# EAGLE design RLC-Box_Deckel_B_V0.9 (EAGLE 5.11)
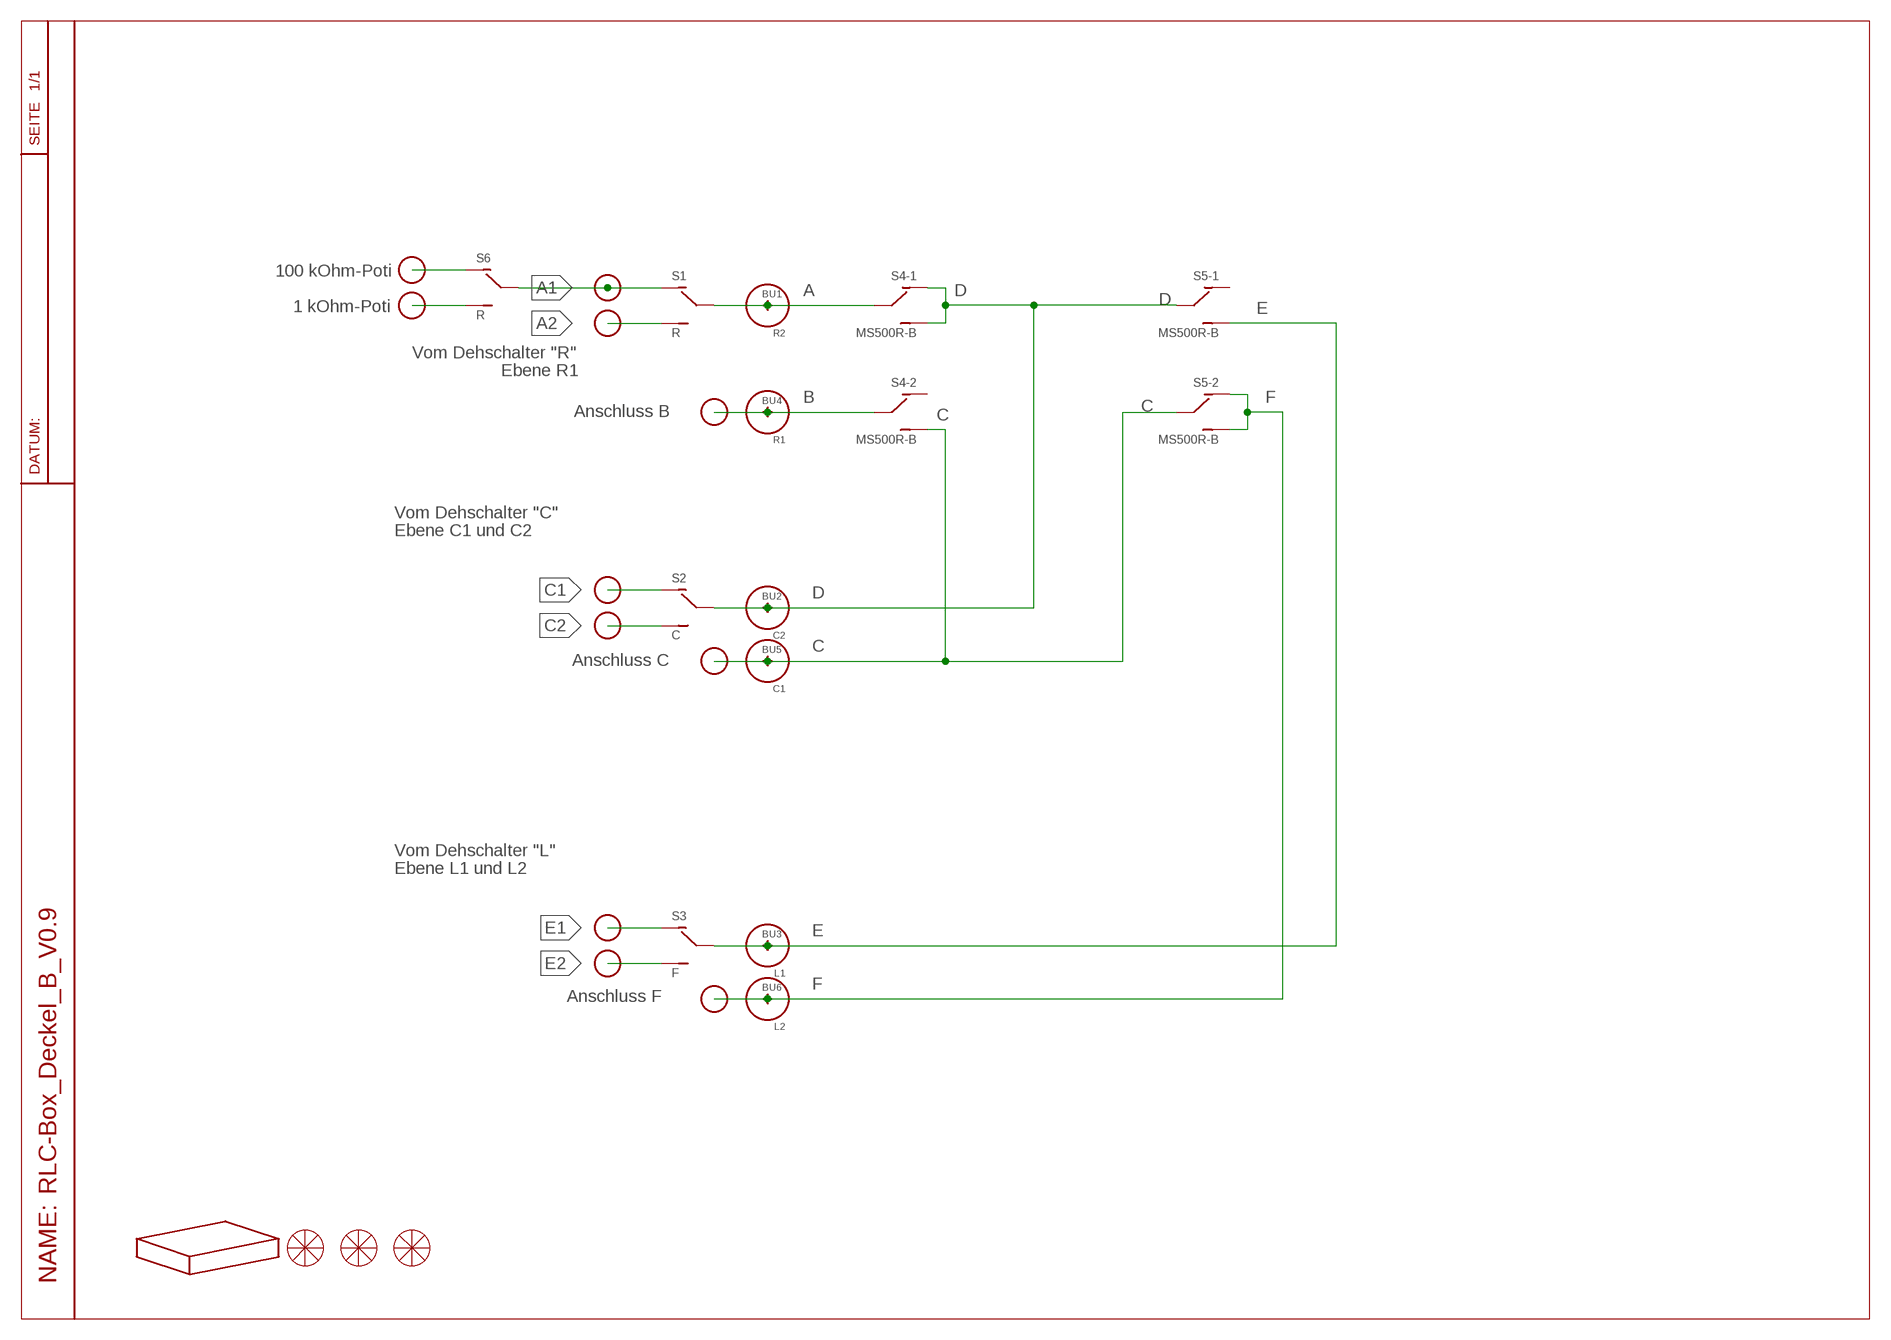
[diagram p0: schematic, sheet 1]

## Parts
BU1  R2  PK10AP  [PK10AP]
BU2  C2  PK10AP  [PK10AP]
BU3  L1  PK10AP  [PK10AP]
BU4  R1  PK10AP  [PK10AP]
BU5  C1  PK10AP  [PK10AP]
BU6  L2  PK10AP  [PK10AP]
P1  PAD-01  PAD-01SMD  [PAD-01-SMD]
P2  PAD-01  PAD-01SMD  [PAD-01-SMD]
P3  PAD-01  PAD-01SMD  [PAD-01-SMD]
P4  PAD-01  PAD-01SMD  [PAD-01-SMD]
P5  PAD-01  PAD-01SMD  [PAD-01-SMD]
P6  PAD-01  PAD-01SMD  [PAD-01-SMD]
P7  PAD-01  PAD-01SMD  [PAD-01-SMD]
P8  PAD-01  PAD-01SMD  [PAD-01-SMD]
P9  PAD-01  PAD-01SMD  [PAD-01-SMD]
P10  PAD-01  PAD-01SMD  [PAD-01-SMD]
P11  PAD-01  PAD-01SMD  [PAD-01-SMD]
S1  R  1XUMT1813  [T8013-1XUM]
S2  C  1XUMT1813  [T8013-1XUM]
S3  F  1XUMT1813  [T8013-1XUM]
S4  MS500R-B  MS500R-BT8011  [T8011-2XUM]
S5  MS500R-B  MS500R-BT8011  [T8011-2XUM]
S6  R  1XUMT1813  [T8013-1XUM]
U$1  DECKEL  [GEHÄUSE]
U$5  SKALA24  SKALA24K  [SKALE24]
U$6  SKALA24  SKALA24K  [SKALE24]
U$9  SKALA24  SKALA24G  [SKALE25-2]

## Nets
A: BU1.1 S1.2 S4.2
A1: P1.P$1 S1.1 S6.2
A2: P2.P$1 S1.3
B: BU4.1 P3.P$1 S4.5
C: BU5.1 P6.P$1 S4.6 S5.5
C1: P4.P$1 S2.1
C2: P5.P$1 S2.3
D: BU2.1 S2.2 S4.1 S4.3 S5.2
E: BU3.1 S3.2 S5.3
E1: P7.P$1 S3.1
E2: P8.P$1 S3.3
F: BU6.1 P9.P$1 S5.4 S5.6
N$1: P10.P$1 S6.1
N$2: P11.P$1 S6.3
Unconnected: S4.4 S5.1

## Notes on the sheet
- 100 kOhm-Poti
- 1 kOhm-Poti
- Vom Dehschalter "R"
- Ebene R1
- Anschluss B
- Vom Dehschalter "C"
- Ebene C1 und C2
- Anschluss C
- Vom Dehschalter "L"
- Ebene L1 und L2
- Anschluss F

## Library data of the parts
BU1-BU6 = MB:PK10AP
P1-P11 = Connect:PAD-01
S1-S3 S6 = Schalter:1XUM
S4 S5 = Schalter:MS500R-B
U$1 = RLC-BOX:DECKEL
U$5 U$6 U$9 = RLC-BOX:SKALA24

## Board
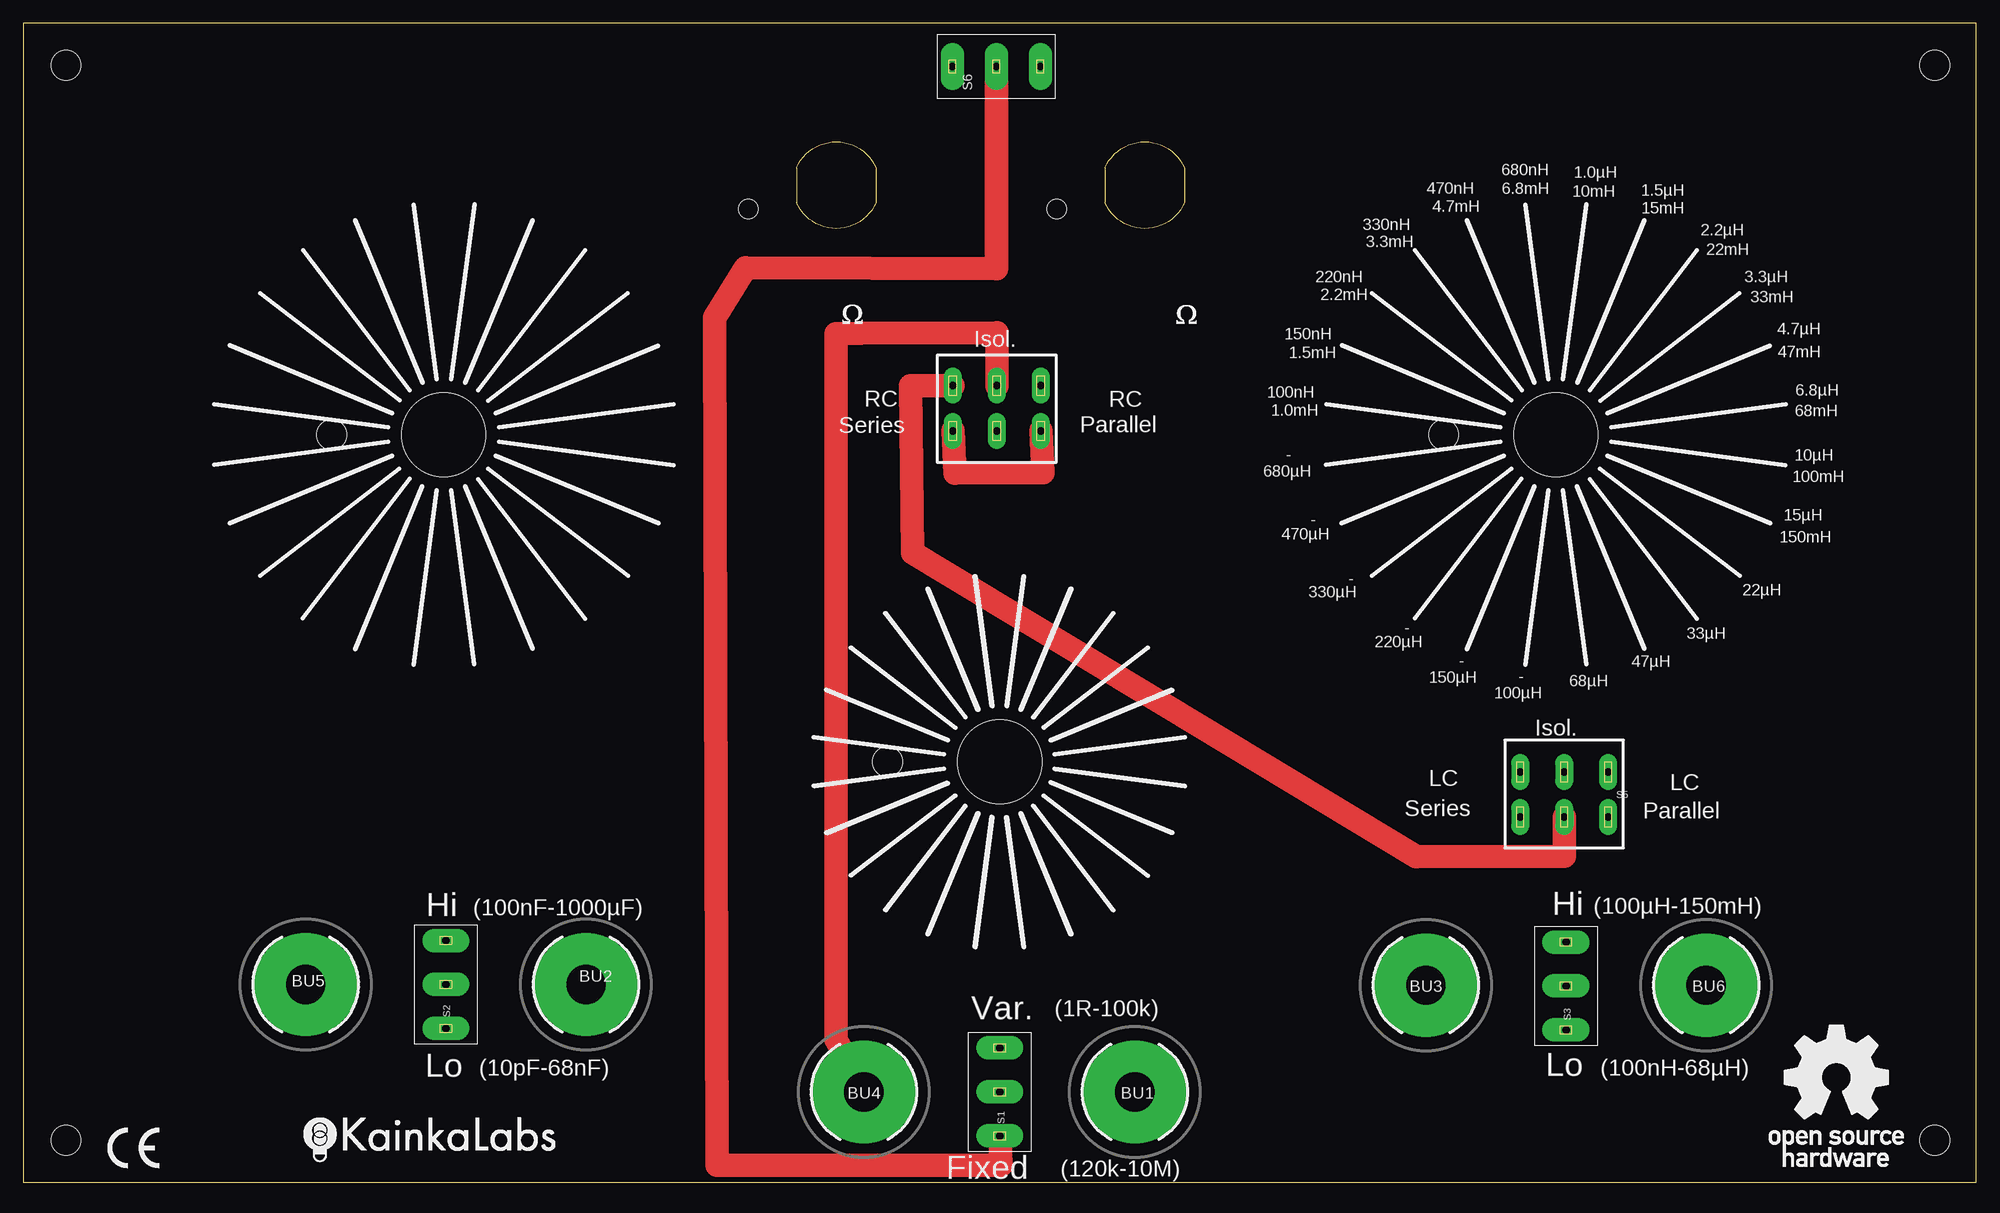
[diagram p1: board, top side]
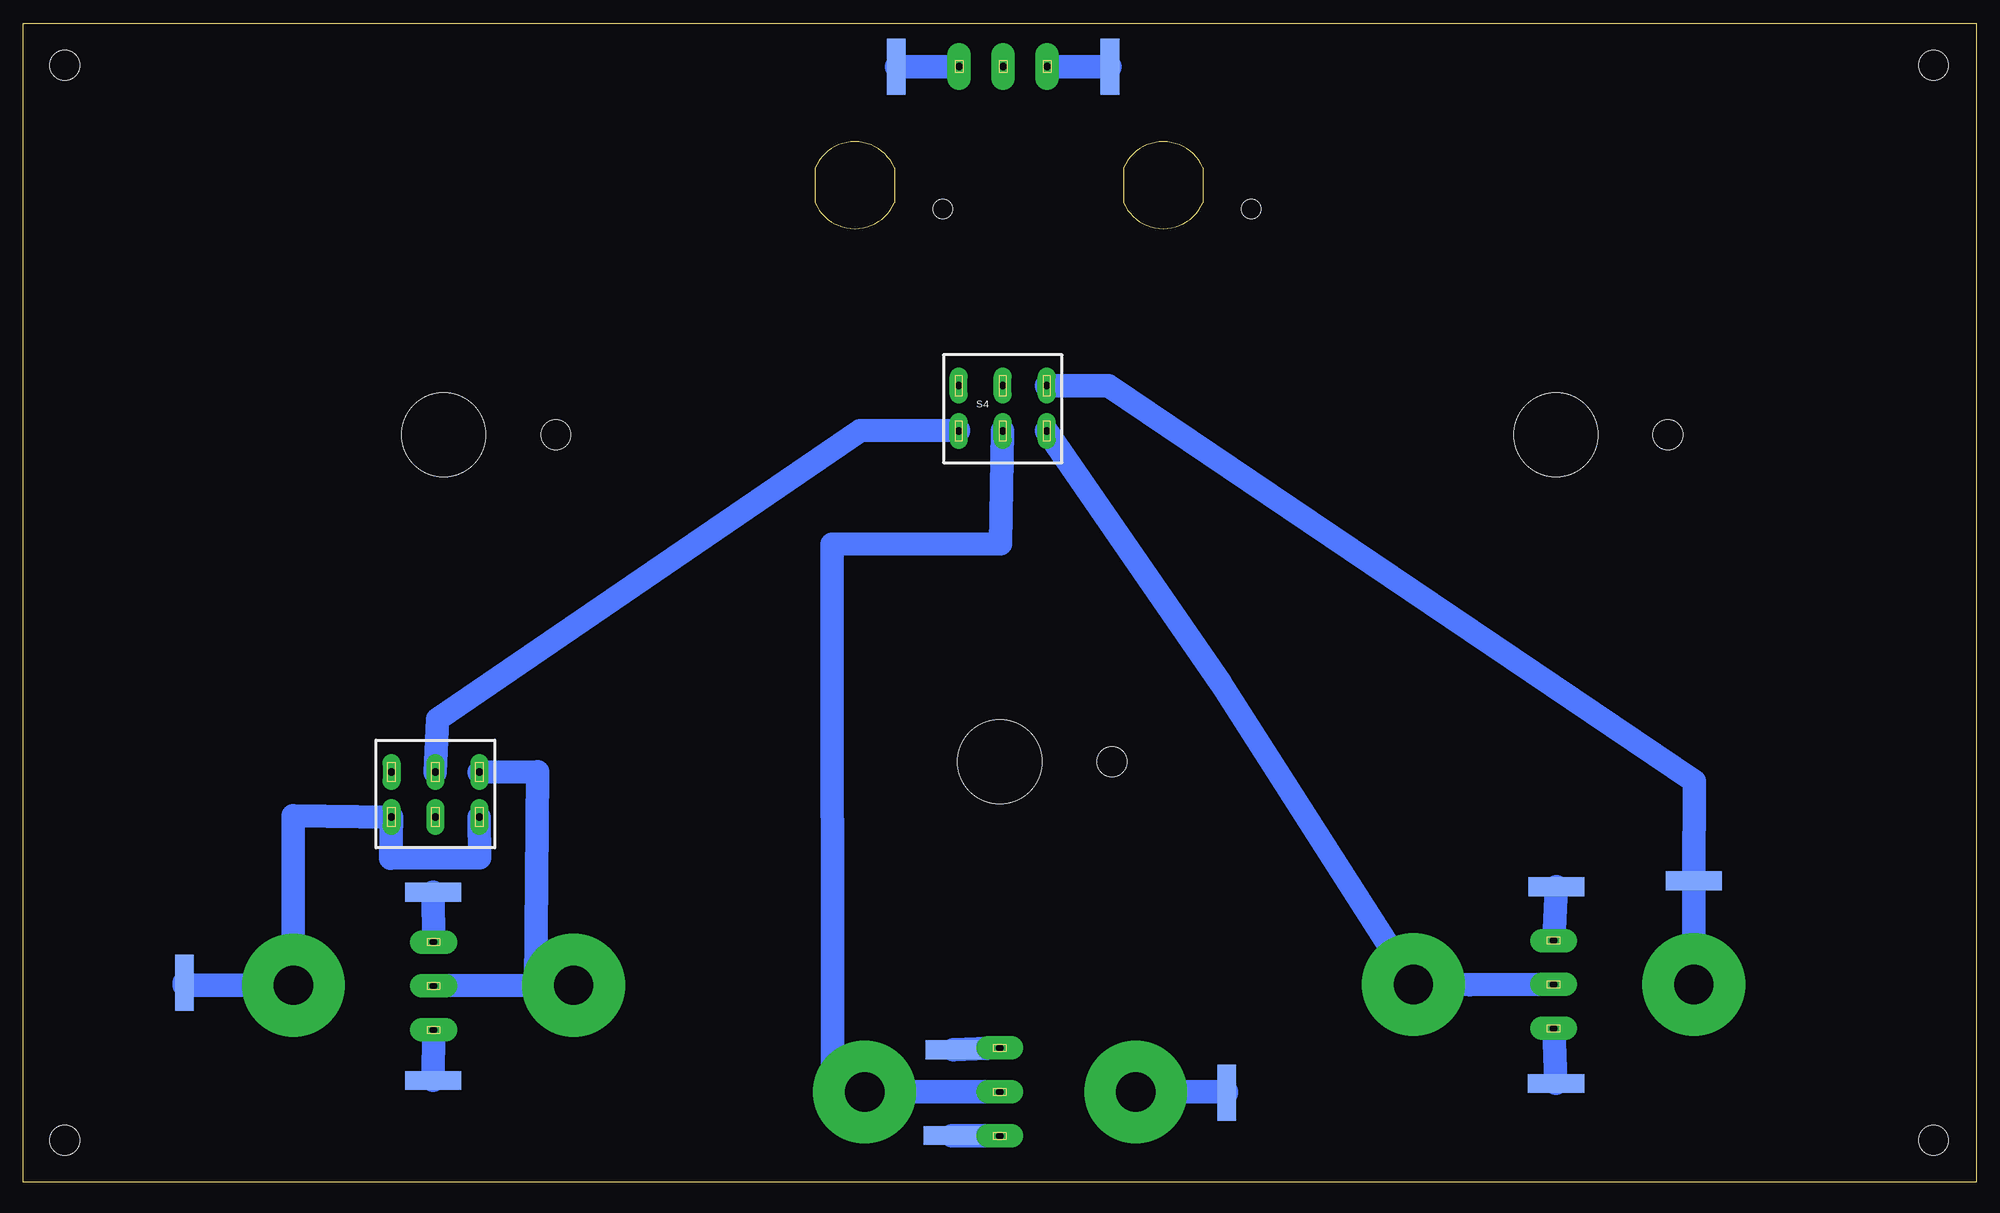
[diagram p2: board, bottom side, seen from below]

Size 209 x 124 mm. Coordinates in mm from the lower left corner, seen from the top.
Copper layers (1*16): Top 0.035mm / dielectric 1.5mm / Bottom 0.035mm
Design rules "default": minimum track width 10mil, minimum drill 23mil, track to track 8mil, track to pad 8mil, pad to pad 8mil, via to via 8mil, smd to smd 8mil, copper to edge 40mil, drill to drill 8mil, minimum pad ring 10mil, minimum via ring 8mil, stop-mask expansion 4mil, vias tented up to drill 0mil, thermal gap 20mil

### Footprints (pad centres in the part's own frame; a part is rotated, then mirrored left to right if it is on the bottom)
PK10AP = drill 4.2 pad 11 round: 1 0,0
PAD-01-SMD = smd 6 x 2: P$1 0,0
T8013-1XUM = drill 0.8 pad 2.54 long: 1 0,4.7; 2 0,0; 3 0,-4.7
T8011-2XUM = drill 0.8 pad 1.93 long: 1 -2.415,4.7; 2 -2.415,0; 3 -2.415,-4.7; 4 2.415,4.7; 5 2.415,0; 6 2.415,-4.7
GEHÄUSE = hole 3.2: 204.567,119.503; 204.567,4.503; 4.567,4.503; 4.567,119.503; 152,80; 92.5,45; 33,80 | hole 9: 164,80; 104.5,45; 45,80
W-POTI-CHN = hole 2.1: -9.411,-2.548

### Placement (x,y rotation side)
BU1  118.96,9.67 0 top
BU2  60.22,21.16 0 top
BU3  150.11,21.09 0 top
BU4  89.96,9.67 0 top
BU5  30.22,21.16 0 top
BU6  180.11,21.09 0 top
P1  109.63,4.99 180 bottom
P2  109.46,14.19 0 bottom
P3  80.22,9.59 270 bottom
P4  44.96,10.57 0 bottom
P5  44.93,31.62 0 bottom
P6  30.23,32.26 180 bottom
P7  165.13,10.9 0 bottom
P8  165.13,31.04 0 bottom
P9  191.77,21.34 270 bottom
P10  92.71,119.38 90 bottom
P11  115.57,119.38 90 bottom
S1  104.5,9.67 180 top
S2  45.22,21.16 180 top
S3  165.1,21 180 top
S4  104.19,82.81 90 bottom
S5  164.9,41.48 270 top
S6  104.14,119.38 90 top
U$1  0,0 0 top
U$2  [KAIKALABS27]  29.97,2.16 0 top
U$3  [CE6MM]  9.02,1.52 0 top
U$4  [OSH15MM]  186.82,1.65 0 top
U$5  104.41,45.02 0 top
U$6  104.5,45 0 top
U$7  SKALA24  [SKALE25-2]  164,80 0 top
U$9  45,80 0 top
U$10  [W-POTI-CHN]  87,106.68 0 top
U$13  [W-POTI-CHN]  120.02,106.68 0 top
U$16  [OHM2MM]  87.59,91.88 0 top
U$17  [OHM2MM]  123.36,91.84 0 top

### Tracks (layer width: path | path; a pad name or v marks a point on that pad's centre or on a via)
A
  Bottom 2.54: S1.2 BU1.1 122.41,9.67 122.45,68.28 104.39,68.33 S4.2
A1
  Top 2.54: S1.1 104.61,1.8 74.23,1.8 73.98,92.5 77.31,97.85 104.14,97.75 S6.2
  Bottom 2.54: S1.1 P1.P$1
A2
  Bottom 2.54: S1.3 P2.P$1
B
  Top 2.54: BU4.1 90.17,9.53 87,15.24 87,90.81 89.59,90.86 104.21,90.9 S4.5
  Bottom 2.54: BU4.1 80.22,9.67 P3.P$1
C
  Top 2.54: S4.6 94.96,85.21 95.15,67.36 149.1,34.82 164.95,34.9 S5.5
  Bottom 2.54: BU5.1 P6.P$1 30.15,42.93 92.86,85.21 S4.6
C1
  Bottom 2.54: P4.P$1 S2.1
C2
  Bottom 2.54: S2.3 P5.P$1
D
  Top 2.54: S4.3 99.69,75.87 109.14,75.92 109.12,75.92 S4.1
  Bottom 0.406: 59.94,21.26 BU2.1
  Bottom 2.54: S2.2 54.18,21.16 59.94,21.26 | BU2.1 80.9,53.44 S4.3 | S5.2 164.65,49.56 119.48,80.41 108.89,80.46 S4.1
E
  Bottom 2.54: BU3.1 S3.2 154.18,21.09 153.97,43.94 S5.3
E1
  Bottom 2.54: P7.P$1 S3.1
E2
  Bottom 2.54: S3.3 P8.P$1
F
  Bottom 2.54: S5.6 160.17,34.7 169.7,34.67 S5.4 180.14,39.19 BU6.1 191.77,21.09 P9.P$1
N$1
  Bottom 2.54: S6.1 P10.P$1
N$2
  Bottom 2.54: S6.3 P11.P$1

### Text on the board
tNames: 680nH | 1.0µH | 470nH | 6.8mH | 1.5µH | 10mH | 4.7mH | 15mH | 330nH | 2.2µH | 3.3mH | 22mH | 220nH | 3.3µH | 2.2mH | 33mH | 4.7µH | 150nH | Isol. | 1.5mH | 47mH | 100nH | 6.8µH | RC | RC | 1.0mH | 68mH | Series | Parallel | - | 10µH | 680µH | 100mH | 15µH | - | 470µH | 150mH | - | 330µH | 22µH | - | 33µH | 220µH | - | 47µH | 150µH | - | 68µH | 100µH | Isol. | LC | LC | Series | Parallel | (100nF-1000µF) | Hi | (100µH-150mH) | Hi | (1R-100k) | Var. | Lo | (10pF-68nF) | Lo | (100nH-68µH) | (120k-10M) | Fixed
tValues: C | L | 680pF | 1.0nF | 470pF | 6.8µF | 10µF | 1.5nF | 4.7µF | 15µF | 2.2nF | 330pF | 3.3µF | 22µF | 3.3nF | 220pF | 33µF | 2.2µF | 1k | 100k | 150pF | 4.7nF | 1.5µF | 47µF | 100pF | 6.8nF | 1.0µF | 68µF | 68pF | 10nF | 680nF | 100µF | 15nF | R | 47pF | 150µF | 470nF | 1.0M | 1.2M | 820k | 1.5M | 33pF | 22nF | 330nF | 220µF | 680k | 1.8M | 33nF | 22pF | 560k | 2.2M | 330µF | 220nF | 15pF | 47nF | 150nF | 10pF | 68nF | 470µF | 470k | 2.7M | 100nF | 1000µF | 390k | 3.3M | 330k | 3.9M | 270k | 4.7M | 220k | 5.6M | 180k | 6.8M | 150k | 8.2M | 120k | 10M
